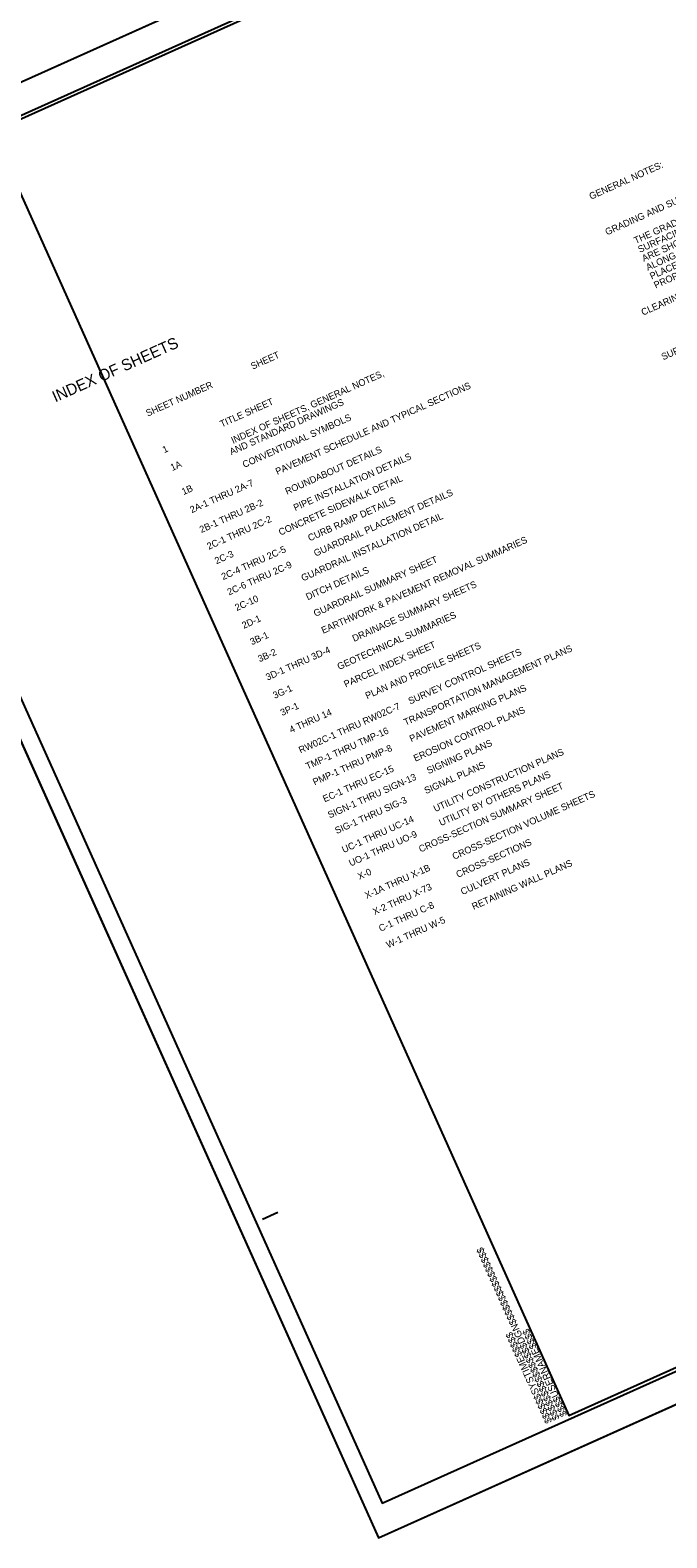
# Model space of a CAD drawing. Extents: x 553377 to 556641, y 502653 to 504402.
# Drawn here: x 554129 to 554604, y 502653 to 503778 of the extents above; entities that cross this region are included whole.
import ezdxf

# ---------------------------------------------------------------- set-up
doc = ezdxf.new("R2010")
doc.units = 0
for name, color, linetype in [('Prop Dimension Text', 7, 'Continuous'), ('Sheet Border Standard 30in CELL', 7, 'Continuous'), ('Sheet Cutting Line CELL', 7, 'Continuous'), ('Sheet Plot Border Inside CELL', 7, 'Continuous'), ('Sheet Plot Border Outside CELL', 7, 'Continuous')]:
    doc.layers.add(name, color=color, linetype=linetype)

msp = doc.modelspace()

# ---------------------------------------------------------------- linework, layer by layer
at = {"layer": 'Sheet Border Standard 30in CELL'}
msp.add_line((554302.7, 502891.2), (554314.1, 502896.4), dxfattribs=at)
msp.add_lwpolyline([(555469.6, 504316.8), (554101.2, 503702.4), (554531.3, 502744.5), (555899.7, 503359)], close=True, dxfattribs=at)
at = {"layer": 'Sheet Cutting Line CELL'}
for p, q in [((555474.9, 504346.6), (553938.6, 503656.8)), ((553938.6, 503656.8), (554389.2, 502653.3)), ((554389.2, 502653.3), (555925.5, 503343.1))]:
    msp.add_line(p, q, dxfattribs=at)
at = {"layer": 'Sheet Plot Border Inside CELL'}
msp.add_lwpolyline([(555480, 504324.3), (553959.7, 503641.6), (554391.9, 502679.1), (555912.2, 503361.8)], close=True, dxfattribs=at)
at = {"layer": 'Sheet Plot Border Outside CELL'}
msp.add_lwpolyline([(555474.9, 504346.6), (553938.6, 503656.8), (554389.2, 502653.3), (555925.5, 503343.1)], close=True, dxfattribs=at)

# ---------------------------------------------------------------- texts
at = {"layer": 'Prop Dimension Text'}
for s, height, rotation, p in [('         SURFACING AT GRADE POINTS SHOWN ON THE TYPICAL SECTIONS.  WHERE NO GRADE LINES ', 5.062, 24.1816, (554568.7, 503605.1)), ('         ARE SHOWN, THE PROFILES SHOWN DENOTE THE TOP ELEVATION OF THE EXISTING PAVEMENT ', 5.062, 24.1816, (554571.7, 503598.5)), ('GENERAL NOTES:                         2024 SPECIFICATIONS', 5.062, 24.1816, (554547.8, 503651.7)), ('         THE GRADE LINES SHOWN DENOTE THE FINISHED ELEVATION OF THE PROPOSED ', 5.062, 24.1816, (554565.7, 503611.8)), ('         ALONG THE CENTER LINE OF SURVEY ON WHICH THE PROPOSED RESURFACING WILL BE ', 5.062, 24.1816, (554574.7, 503591.8)), ('GRADING AND SURFACING OR RESURFACING AND WIDENING:  ', 5.062, 24.1816, (554559.7, 503625.1)), ('         PLACED.  GRADE LINES MAY BE ADJUSTED BY THE ENGINEER IN ORDER TO SECURE A ', 5.062, 24.1816, (554577.6, 503585.2)), ('         PROPER TIE-IN.  ', 5.062, 24.1816, (554580.6, 503578.5)), ('CLEARING:  ', 5.062, 24.1816, (554586.6, 503565.2)), ('SUPERELEVATION:  ', 5.062, 24.1816, (554601.6, 503531.9)), ('                        INDEX OF SHEETS ', 8.438, 24.1169, (554079.5, 503469.7)), ('SHEET NUMBER                 SHEET   ', 5.063, 24.1169, (554217.1, 503489.9)), ('1A                      INDEX OF SHEETS, GENERAL NOTES, ', 5.063, 24.1169, (554235.4, 503449.3)), ('2A-1 THRU 2A-7          PAVEMENT SCHEDULE AND TYPICAL SECTIONS', 5.063, 24.1169, (554249.9, 503417.8)), ('1                       TITLE SHEET', 5.063, 24.1169, (554229.4, 503462.6)), ('                        AND STANDARD DRAWINGS', 5.063, 24.1169, (554238.3, 503442.7)), ('1B                      CONVENTIONAL SYMBOLS ', 5.063, 24.1169, (554243.8, 503431.3)), ('2B-1 THRU 2B-2          ROUNDABOUT DETAILS', 5.063, 24.1169, (554257.1, 503403)), ('2C-1 THRU 2C-2          PIPE INSTALLATION DETAILS', 5.063, 24.1169, (554262.6, 503390.5)), ('2C-3                    CONCRETE SIDEWALK DETAIL', 5.063, 24.1169, (554268.4, 503379.7)), ('2C-4 THRU 2C-5          CURB RAMP DETAILS', 5.063, 24.1169, (554273.4, 503367.9)), ('2C-6 THRU 2C-9          GUARDRAIL PLACEMENT DETAILS', 5.063, 24.1169, (554277.8, 503356.5)), ('2C-10                   GUARDRAIL INSTALLATION DETAIL', 5.063, 24.1169, (554283.5, 503344.8)), ('3B-2                    EARTHWORK & PAVEMENT REMOVAL SUMMARIES', 5.063, 24.1169, (554300.6, 503306.6)), ('3B-1                    GUARDRAIL SUMMARY SHEET', 5.063, 24.1169, (554294.8, 503319.3)), ('2D-1                    DITCH DETAILS', 5.063, 24.1169, (554288.7, 503331.5)), ('3D-1 THRU 3D-4          DRAINAGE SUMMARY SHEETS', 5.063, 24.1169, (554306.5, 503292.9)), ('3G-1                    GEOTECHNICAL SUMMARIES', 5.063, 24.1169, (554311.8, 503279.3)), ('3P-1                    PARCEL INDEX SHEET', 5.063, 24.1169, (554317.4, 503266.5)), ('4 THRU 14               PLAN AND PROFILE SHEETS', 5.063, 24.1169, (554324.1, 503253.7)), ('RW02C-1 THRU RW02C-7    SURVEY CONTROL SHEETS', 5.063, 24.1169, (554331.1, 503238.5)), ('TMP-1 THRU TMP-16       TRANSPORTATION MANAGEMENT PLANS', 5.063, 24.1169, (554336.3, 503226.5)), ('PMP-1 THRU PMP-8        PAVEMENT MARKING PLANS', 5.063, 24.1169, (554341.6, 503214.7)), ('EC-1 THRU EC-15         EROSION CONTROL PLANS', 5.063, 24.1169, (554349.1, 503202.1)), ('SIGN-1 THRU SIGN-13     SIGNING PLANS', 5.063, 24.1169, (554352.8, 503190.1)), ('UC-1 THRU UC-14         UTILITY CONSTRUCTION PLANS', 5.063, 24.1169, (554363.3, 503164.2)), ('SIG-1 THRU SIG-3        SIGNAL PLANS', 5.063, 24.1169, (554358.1, 503178.4)), ('UO-1 THRU UO-9          UTILITY BY OTHERS PLANS', 5.063, 24.1169, (554368.5, 503154.2)), ('X-0                     CROSS-SECTION SUMMARY SHEET', 5.063, 24.1169, (554375, 503144.2)), ('X-1A THRU X-1B          CROSS-SECTION VOLUME SHEETS', 5.063, 24.1169, (554380.4, 503130)), ('X-2 THRU X-73           CROSS-SECTIONS', 5.063, 24.1169, (554386.3, 503117.9)), ('C-1 THRU C-8            CULVERT PLANS', 5.063, 24.1169, (554390.8, 503105.5)), ('W-1 THRU W-5            RETAINING WALL PLANS', 5.063, 24.1169, (554396.4, 503093.2))]:
    msp.add_text(s, height=height, rotation=rotation, dxfattribs=at).set_placement(p)
at = {"layer": 'Sheet Border Standard 30in CELL'}
for s, p in [('$$$$$$$$$$$$$$$$DGN$$$$$$$$$$$$$$$$', (554524.5, 502742.4)), ('$$$$$$SYSTIME$$$$$', (554518.9, 502740.1)), ('$$$$USERNAME$$$$', (554530.2, 502745.1))]:
    msp.add_text(s, height=5.25, rotation=114.1816, dxfattribs=at).set_placement(p)

doc.saveas('drawing.dxf')
